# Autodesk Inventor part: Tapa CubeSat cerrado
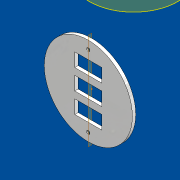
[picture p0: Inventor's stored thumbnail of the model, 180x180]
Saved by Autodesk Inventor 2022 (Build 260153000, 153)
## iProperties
Created: 2022-05
Part Number: Tapa CubeSat cerrado
Material: LCP Plastic
Document SubType Name: Modeling
Designer: Daniel
Density: 1.626 g/cm^3
Appearance: Smooth - White
Author: Daniel
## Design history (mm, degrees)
workplane "Work Plane1"
sketch "Sketch2"
  geometry: L1 (-10, -5)-(10, -5); L2 (10, -5)-(10, 5); L3 (10, 5)-(-10, 5); L4 (-10, 5)-(-10, -5); L5 (-10, -5)-(10, 5); L6 (10, -5)-(-10, 5); L7 (-10, 20)-(10, 20); L8 (10, 20)-(10, 10); L9 (10, 10)-(-10, 10); L10 (-10, 10)-(-10, 20); L11 (-10, -10)-(10, -10); L12 (10, -10)-(10, -20); L13 (10, -20)-(-10, -20); L14 (-10, -20)-(-10, -10); 1 further point
  constraints: 28 end point, 6 parallel, 3 horizontal, 3 perpendicular, 2 midpoint, 2 point on line
  dimensions: "d9" = 20 distance of L3.end L2.end; "d10" = 10 distance of L2.end L1.end; "d11" = 20 distance of L7.start L7.end (= d9); "d12" = 20 distance of L12.end L13.end (= d9); "d14" = 5 distance between parallel lines of L3 L9; "d15" = 10 distance of L7.end L8.end; "d16" = 10 distance of L11.end L12.end; "d17" = 5 distance between parallel lines of L1 L11 (= d14)
sketch "Sketch3"
  geometry: C1 r 1.5 at (0, -27.5); C2 r 32.5 at (0, 0); C3 r 1.5 at (22.248, 16.164); C4 r 1.5 at (-22.248, 16.164); 2 further points
  constraints: 4 centre point
  dimensions: "d24" = 3 diameter of C4; "d25" = 65 diameter of C2; "d26" = 27.5 distance of point (0, 0) C4.centre; "d27" = 27.5 distance of C3.centre point (0, 0); "d28" = 27.5 distance of C1.centre point (0, 0); "d29" = 16.16409 vertical distance of point (0, 0) C4.centre; "d30" = 16.16409 vertical distance of point (0, 0) C3.centre; "d31" = 0 horizontal distance of C1.centre point (0, 0); "d32" = 3 diameter of C1 (= d24); "d33" = 3 diameter of C3 (= d24)
extrude "Extrusion3" new body sketch "Sketch3" distance "d20" = 2.5; taper "d21" = 0 deg
extrude "Extrusion4" cut sketch "Sketch2" distance "d22" = 2.5; taper "d23" = 0 deg
workplane "Work Plane2"
sketch "Boceto4"
  geometry: L1 (-10, -20)-(-10, -10) reference; L2 (-10, -10)-(10, -10) reference; L3 (10, -10)-(10, -20) reference; L4 (10, -20)-(-10, -20) reference; L5 (-10, 5)-(10, 5) reference; L6 (10, 5)-(10, -5) reference; L7 (10, -5)-(-10, -5) reference; L8 (-10, -5)-(-10, 5) reference; L9 (-10, 10)-(-10, 20) reference; L10 (-10, 20)-(10, 20) reference; L11 (10, 20)-(10, 10) reference; L12 (10, 10)-(-10, 10) reference; C1 r 32.5 at (0, 0) reference; C2 r 1.5 at (22.248, 16.164) reference; C3 r 1.5 at (-22.248, 16.164) reference; C4 r 1.5 at (0, -27.5) reference; 1 further point
extrude "Extrusión5" join sketch "Boceto4" stored distance "d34" = 0; taper "d35" = 0 deg
sketch "Boceto5"
  geometry: 1 further point
sketch "Boceto7"
  geometry: C1 r 1.5 at (0, -26.5) reference; A1 r 26.5 centre (0, 0) between (0, -26.5) and (0, 26.5); 2 further points
  constraints: 2 coincident, 2 point on circle, 1 centre point
hole "Agujero2" sketch "Boceto7" at (0, -26.5), (0, 26.5) diameter "d43" = 2.5; stored, may be unused: countersink angle "d47" = 90 deg, drill point angle "d49" = 118 deg; dims "d44" = 6, "d45" = 6.3, "d46" = 2, "d48" = 8
body "Solid2"
sketch "Sketch1"
  geometry: C1 r 1.5 at (0, 27.5); C2 r 1.5 at (-23.816, -13.75); C3 r 1.5 at (23.816, -13.75); 1 further point
  constraints: 3 centre point, 7 other
  dimensions: "d5" = 360 deg dimension on point (0, 0) C1.centre (derived)
node "Contorno proyectado1"
node "Referencia3"
